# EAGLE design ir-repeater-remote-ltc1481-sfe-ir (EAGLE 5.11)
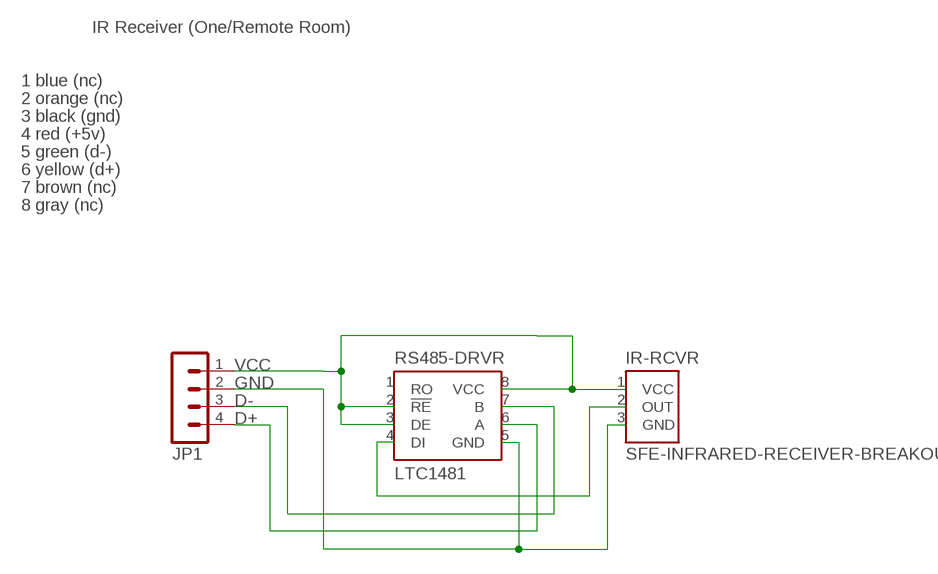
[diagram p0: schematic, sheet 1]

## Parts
IR-RCVR  SFE-INFRARED-RECEIVER-BREAKOUT  [3SIL]
JP1  MA04-1  [MA04-1]
RS485-DRVR  LTC1481  [8DIP]

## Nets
D+: JP1.4 RS485-DRVR.6(A)
D-: JP1.3 RS485-DRVR.7(B)
GND: IR-RCVR.3(GND) JP1.2 RS485-DRVR.5(GND)
N$6: IR-RCVR.2(OUT) RS485-DRVR.4(DI)
VCC: IR-RCVR.1(VCC) JP1.1 RS485-DRVR.2(!RE) RS485-DRVR.3(DE) RS485-DRVR.8(VCC)
Unconnected: RS485-DRVR.1(RO)

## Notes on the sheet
- IR Receiver (One/Remote Room)
- 1 blue (nc)
- 2 orange (nc)
- 3 black (gnd)
- 4 red (+5v)
- 5 green (d-)
- 6 yellow (d+)
- 7 brown (nc)
- 8 gray (nc)

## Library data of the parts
IR-RCVR = trl:SFE-INFRARED-RECEIVER-BREAKOUT
JP1 = con-lstb:MA04-1: PIN HEADER; OC_FARNELL: unknown; OC_NEWARK: unknown
RS485-DRVR = trl:LTC1481

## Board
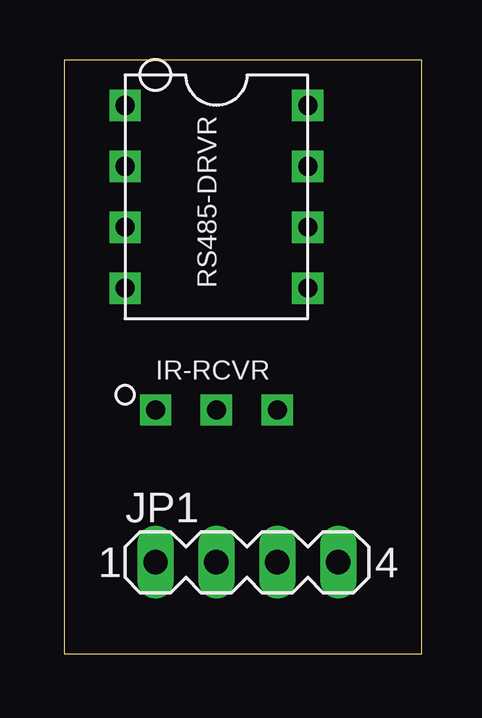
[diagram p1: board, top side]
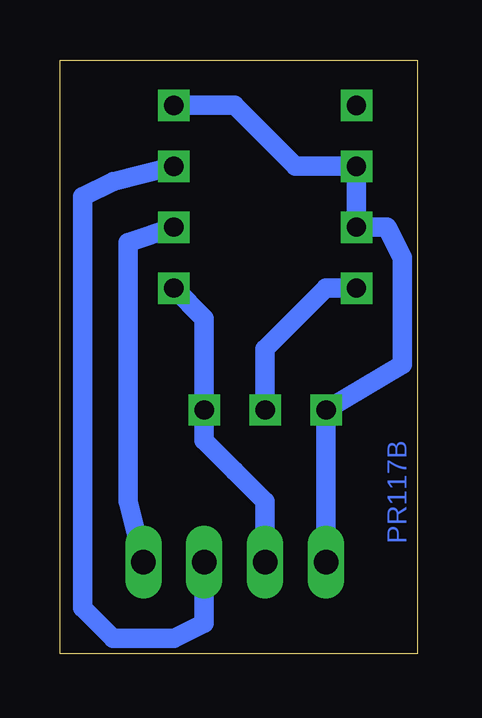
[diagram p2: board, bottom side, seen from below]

Size 14.91 x 24.75 mm. Coordinates in mm from the lower left corner, seen from the top.
Outline: 0,0 14.91,0 14.91,24.75 0,24.75 0,0
Copper layers (1*16): Top 0.035mm / dielectric 1.5mm / Bottom 0.035mm
Design rules "default": minimum track width 10mil, minimum drill 24mil, track to track 8mil, track to pad 8mil, pad to pad 8mil, via to via 8mil, smd to smd 8mil, copper to edge 40mil, drill to drill 8mil, minimum pad ring 10mil, minimum via ring 8mil, stop-mask expansion 4mil, vias tented up to drill 0mil, thermal gap 10mil

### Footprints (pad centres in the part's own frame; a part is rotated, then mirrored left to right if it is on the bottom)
3SIL = drill 0.8 square: 1 -2.54,0; 2 0,0; 3 2.54,0
MA04-1 = drill 1.016 long: 1 -3.81,0; 2 -1.27,0; 3 1.27,0; 4 3.81,0
8DIP = drill 0.8 square: 1 -3.81,3.81; 2 -3.81,1.27; 3 -3.81,-1.27; 4 -3.81,-3.81; 5 3.81,-3.81; 6 3.81,-1.27; 7 3.81,1.27; 8 3.81,3.81

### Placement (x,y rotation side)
IR-RCVR  6.35,10.16 0 top
JP1  7.62,3.81 0 top
RS485-DRVR  6.35,19.05 0 top

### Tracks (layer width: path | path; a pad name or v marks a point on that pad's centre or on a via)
D+
  Bottom 0.813: JP1.4 12.06,6.35 12.06,17.14 RS485-DRVR.6
D-
  Bottom 0.813: JP1.3 8.89,1.27 10.16,0.64 12.7,0.64 13.97,1.91 13.97,19.05 12.7,19.68 RS485-DRVR.7
GND
  Bottom 0.813: 7.62,7.62 8.89,8.89 | 7.62,7.62 8.89,8.89 | 8.89,8.89 IR-RCVR.3 8.89,13.97 RS485-DRVR.5 | 7.62,7.62 8.89,8.89 | JP1.2 6.35,6.35 7.62,7.62
N$6
  Bottom 0.813: RS485-DRVR.4 3.81,15.24 6.35,12.7 IR-RCVR.2
VCC
  Bottom 0.813: RS485-DRVR.8 7.62,22.86 5.08,20.32 RS485-DRVR.2 RS485-DRVR.3 1.27,17.78 0.64,16.51 0.64,13.97 0.64,12.06 IR-RCVR.1 JP1.1

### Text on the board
Bottom: PR117B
